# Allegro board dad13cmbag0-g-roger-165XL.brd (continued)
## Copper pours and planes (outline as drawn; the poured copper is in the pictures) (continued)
SWR_GND on IN2 (solid shape): 103.61,39.45 104.07,39.45 104.18,39.35 104.18,37.09 103.87,36.78 102.47,36.78 102.35,36.66 102.17,36.66 102.17,36.7 102.12,36.84 102.01,36.95 101.96,37.04 102.01,37.12 101.81,37.78 101.62,37.12 101.66,37.04 101.62,36.95 101.51,36.84 101.46,36.7 101.45,36.66 100.95,36.66 100.54,36.25 100.54,35.87 100.31,35.64 97.34,35.64 97.11,35.87 97.11,37.14 96.71,37.55 95.95,37.55 95.84,37.65 95.84,39.35 96.08,39.58 97.09,39.58 97.88,40.37 102.7,40.37
SWR_GND on SGND1 (solid shape): 103.54,39.52 103.62,39.47 103.72,39.45 104.07,39.45 104.18,39.35 104.18,37.09 103.87,36.78 102.58,36.78 102.48,36.76 102.4,36.71 102.34,36.66 102.17,36.66 101.81,37.01 101.46,36.66 101.05,36.66 100.95,36.64 100.87,36.58 100.62,36.33 100.56,36.25 100.54,36.15 100.54,35.87 100.31,35.64 97.35,35.64 97.11,35.87 97.11,37.04 97.1,37.14 97.04,37.22 96.79,37.47 96.7,37.53 96.61,37.55 95.95,37.55 95.84,37.65 95.84,39.35 96.08,39.58 96.99,39.58 97.08,39.6 97.17,39.65 97.88,40.36 102.7,40.36
SWR_GND on SVCC (solid shape): 103.54,39.52 103.62,39.47 103.72,39.45 104.07,39.45 104.18,39.35 104.18,37.09 103.87,36.78 102.58,36.78 102.48,36.76 102.4,36.71 102.34,36.66 102.17,36.66 101.81,37.01 101.46,36.66 101.05,36.66 100.95,36.64 100.87,36.58 100.62,36.33 100.56,36.25 100.54,36.15 100.54,35.87 100.31,35.64 97.35,35.64 97.11,35.87 97.11,37.04 97.1,37.14 97.04,37.22 96.79,37.47 96.7,37.53 96.61,37.55 95.95,37.55 95.84,37.65 95.84,39.35 96.08,39.58 96.99,39.58 97.08,39.6 97.17,39.65 97.88,40.36 102.7,40.36
SWR_GND on IN3 (solid shape): 103.41,39.65 103.41,39.22 102.9,39.22 101.6,37.93 101.17,37.93 99.53,36.28 99.53,35.69 99.48,35.64 97.34,35.64 97.11,35.87 97.11,37.14 96.71,37.55 95.95,37.55 95.84,37.65 95.84,39.35 96.07,39.58 97.09,39.58 97.88,40.37 102.7,40.37
SWR_GND on IN4 (solid shape): 103.61,39.45 104.07,39.45 104.18,39.35 104.18,37.09 103.87,36.78 102.47,36.78 102.35,36.66 102.17,36.66 102.17,36.7 102.12,36.84 102.01,36.95 101.96,37.04 102.01,37.12 101.81,37.78 101.62,37.12 101.66,37.04 101.62,36.95 101.51,36.84 101.46,36.7 101.45,36.66 100.95,36.66 100.54,36.25 100.54,35.87 100.31,35.64 97.34,35.64 97.11,35.87 97.11,37.14 96.71,37.55 95.95,37.55 95.84,37.65 95.84,39.35 96.08,39.58 97.09,39.58 97.88,40.37 102.7,40.37
SWR_GND on GND2 (solid shape): 103.61,39.45 104.07,39.45 104.18,39.35 104.18,37.09 103.87,36.78 102.47,36.78 102.34,36.66 102.24,36.66 102.19,36.7 102.19,36.72 102.13,36.86 102.03,36.97 101.99,37.05 102.03,37.13 101.81,37.78 101.6,37.13 101.64,37.05 101.6,36.97 101.49,36.86 101.44,36.72 101.43,36.7 101.38,36.66 100.95,36.66 100.54,36.25 100.54,35.87 100.31,35.64 97.35,35.64 97.11,35.87 97.11,37.14 96.71,37.55 95.95,37.55 95.84,37.65 95.84,39.35 96.08,39.58 97.09,39.58 97.88,40.37 102.7,40.37
VCHGR_BST on TOP (solid shape): 127.9,29.16 127.64,28.91 127.64,27.54 127.67,27.51 126.93,27.51 126.93,28.55 127.62,29.24 127.62,30.38 127.9,30.38
VCHGR_DH on TOP (solid shape): 128.38,29.13 128.34,29.09 128.34,28.99 128.34,28.35 128.29,28.3 127.91,28.3 127.77,28.44 127.77,28.81 128.13,29.16 128.13,30.38 128.38,30.38
VCHGR_DH on BOTTOM (solid shape): 130.46,17.15 130.46,16.31 130.26,16.11 129.22,16.11 129.09,16.24 129.09,16.69 129.6,17.2 130.41,17.2
VCHGR_DL on BOTTOM (solid shape): 126.17,20.53 126.17,19.03 126.15,19 125.36,19 125.33,19.03 125.33,20.58 125.51,20.76 125.94,20.76
VCHGR_LX on TOP (solid shape): 128.89,29.16 129.04,29.01 129.04,28.38 128.89,28.22 128.89,27.18 128.79,27.08 128.31,27.08 128.31,27.56 128.47,27.73 128.47,28.28 128.51,28.32 128.51,29.06 128.61,29.16 128.61,30.38 128.89,30.38
VCHGR_LX on BOTTOM (solid shape): 129.19,19.28 129.19,17.05 128.97,16.82 128.97,16.08 129.09,15.96 130.54,15.96 130.79,16.21 130.79,17.15 130.85,17.2 134.88,17.2 135.24,16.84 135.24,14.3 134.17,13.24 130.82,13.24 130.13,13.92 127.16,13.92 126.92,14.16 131.56,14.16 131.56,14.11 131.58,14.05 131.6,14 131.63,13.96 131.66,13.91 131.7,13.88 131.75,13.84 131.8,13.82 131.85,13.8 131.91,13.8 131.97,13.8 132.02,13.8 132.07,13.82 132.12,13.84 132.17,13.88 132.21,13.91 132.25,13.96 132.28,14 132.3,14.05 132.31,14.11 132.32,14.16 132.32,14.22 132.31,14.27 132.29,14.33 132.26,14.38 132.23,14.42 132.19,14.46 132.15,14.5 132.1,14.52 132.05,14.54 131.99,14.56 131.94,14.56 131.88,14.56 131.83,14.54 131.78,14.52 131.73,14.5 131.68,14.46 131.64,14.42 131.61,14.38 131.59,14.33 131.57,14.27 131.56,14.22 131.56,14.16 126.92,14.16 126.78,14.3 126.78,19.27 126.85,19.34 129.13,19.34
VCHGR_VCC on TOP (solid shape): 129.63,30.23 129.63,29.67 130.77,28.53 132.04,28.53 132.39,28.17 132.39,26.52 132.37,26.5 130.77,26.5 130.13,27.13 129.5,27.13 129.37,27.26 129.37,29.16 129.12,29.42 129.12,30.31 129.19,30.38 129.47,30.38
VCORE_AGND on IN2 (solid shape): outline of 1112 points within 17.68,51.07 30.31,61.37
N122118059 on TOP (solid shape): 134.71,41.48 134.71,40.21 133.92,39.43 131.62,39.43 131.62,41.19 131.68,41.25 132.06,41.25 132.06,40.37 132.37,40.37 132.37,41.25 132.72,41.25 132.72,40.37 133.03,40.37 133.03,41.25 133.49,41.25 134.05,41.81 134.38,41.81
N122232203 on TOP (solid shape): 69.63,56.37 70.57,56.37 70.7,56.24 70.7,54.89 70.52,54.72 68.95,54.72 68.74,54.92 68.74,56.39 68.79,56.44 69.56,56.44
N122232731 on TOP (solid shape): 87.46,46.54 87.46,45.75 87.39,45.67 86.57,45.67 86.45,45.8 84.67,45.8 84.54,45.93 84.54,46.46 84.64,46.56 87.44,46.56
N122232990 on IN1 (solid shape): 69.45,57.18 69.45,56.37 69.35,56.27 69.05,56.27 68.26,55.48 67.83,55.48 67.7,55.61 67.7,56.42 67.93,56.65 68.49,56.65 69.1,57.26 69.38,57.26
N122232990 on IN4 (solid shape): 69.48,57.31 69.48,56.77 69.63,56.62 69.66,56.62 69.73,56.54 69.73,56.44 69.61,56.32 69,56.32 68.64,56.67 68.64,57.26 68.82,57.43 69.35,57.43
N122416321 on TOP (solid shape): 185.68,56.16 185.68,53.73 185.63,53.67 184.35,53.67 184.31,53.71 184.31,54.41 183.63,55.1 183.63,56.01 183.8,56.19 185.66,56.19
N122446326 on BOTTOM (solid shape): 101.81,54.06 101.81,52.28 101.69,52.15 98.89,52.15 98.77,52.28 98.77,53.01 98.51,53.27 98.51,54.26 98.55,54.3 101.57,54.3
N122457781 on TOP (solid shape): 183.18,39.11 183.18,37.69 182.69,37.19 182.69,36.35 182.99,36.05 182.99,35.46 182.96,35.43 182.51,35.43 182.46,35.48 182.46,35.67 182.2,35.92 182.2,38.38 182.22,38.4 182.22,39.13 182.48,39.4 182.89,39.4
N122457865 on TOP (solid shape): 183.75,32.65 183.75,32.06 183.57,31.88 183.32,31.88 182.89,31.45 182.89,31.02 183.5,30.41 183.5,29.86 183.47,29.83 182.97,29.83 182.92,29.89 182.92,30.18 182.25,30.84 182.25,31.73 182.71,32.19 182.71,32.62 182.94,32.85 183.55,32.85
N122829159 on TOP (solid shape): 141.74,41.68 141.74,41.08 142.1,40.73 143.06,40.73 143.21,40.58 143.21,39.33 143.15,39.28 140.67,39.28 140.15,39.28 140.06,39.36 140.06,40.86 141.06,41.85 141.58,41.85
N122829607 on TOP (solid shape): 157.92,39.81 157.92,39.48 157.01,38.56 157.01,38.05 156.98,38.03 156.22,38.03 156.19,38.05 156.19,40.01 156.25,40.06 157.67,40.06
N122832375 on TOP (solid shape): 125.18,37.39 125.18,35.97 124.67,35.46 123.45,35.46 123.45,35.72 122.49,35.72 122.49,35.34 121.98,34.83 120.2,34.83 120.15,34.88 120.15,35.62 120.46,35.92 121.6,35.92 121.7,36.02 121.7,36.73 121.83,36.86 124.01,36.86 124.7,37.55 125.03,37.55
N122832615 on TOP (solid shape): 119.82,32.16 119.82,31.42 119.75,31.35 117.76,31.35 117.71,31.4 117.71,32.19 117.82,32.29 119.69,32.29
N122833803 on TOP (solid shape): 102.47,66.22 102.47,65.84 102.37,65.74 102.07,65.74 101.18,64.85 100.31,64.85 100.26,64.9 100.26,66.27 100.34,66.35 102.35,66.35
N122833805 on BOTTOM (solid shape): 102.94,64.86 103.51,64.86 104.17,64.21 104.17,63.99 103.17,63.99 103.17,63.78 104.17,63.78 104.17,63.59 103.17,63.59 103.17,63.39 104.17,63.39 104.17,63.19 103.17,63.19 103.17,62.99 104.17,62.99 104.17,62.81 104.15,62.8 102.83,62.8 102.83,62.79 102.42,62.79 102.14,62.51 102.14,61.6 101.66,61.12 101.66,60.71 100.82,59.87 100.82,58.73 100.75,58.65 99.4,58.65 98.13,59.92 98.13,65.03 98.18,65.08 102.73,65.08
N122833835 on BOTTOM (solid shape): 103.15,62.59 104.15,62.59 104.17,62.58 104.17,62.41 104.15,62.39 103.12,62.39 103.12,62.39 102.98,62.39 102.93,62.34 102.93,61.45 102.63,61.14 102.63,58.81 102.5,58.68 101.36,58.68 101.25,58.78 101.25,60.05 101.81,60.61 101.81,61.07 102.3,61.55 102.3,62.41 102.5,62.62 103.12,62.62
N122833837 on BOTTOM (solid shape): 102.04,57.23 99.27,57.23 99.1,57.41 99.1,57.81 99.32,58.04 102.04,58.04
N122834634 on BOTTOM (solid shape): 181.43,10.47 182.68,10.47 182.69,10.46 182.69,10.17 181.71,10.17 181.71,9.97 182.69,9.97 182.69,9.67 181.71,9.67 181.71,9.47 182.69,9.47 182.69,9.2 182.67,9.18 181.37,9.18 181.18,8.99 181.18,8.19 181.17,8.19 179.2,8.19 179.16,8.23 179.16,10.66 179.18,10.68 181.22,10.68
N122836623 on BOTTOM (solid shape): 16.62,58.91 17.23,58.91 17.31,58.83 17.31,58.37 17.21,58.27 16.57,58.27 16.47,58.17 15.48,58.17 15.45,58.2 15.45,59.01 15.53,59.08 16.44,59.08
N122836643 on BOTTOM (solid shape): 17.26,57.94 17.26,57.18 17.24,57.17 17.24,56.74 17.02,56.51 16.7,56.51 15.99,55.8 15.99,55.16 15.96,55.14 15.83,55.14 15.8,55.17 15.8,56.02 16.65,56.88 16.65,57.99 16.67,58.02 17.18,58.02
N122836645 on BOTTOM (solid shape): 16.24,57.56 16.24,56.8 15.58,56.14 15.58,55.15 15.53,55.1 15.45,55.1 15.4,55.15 15.4,56.17 15.38,56.19 15.38,57.51 15.48,57.61 16.19,57.61
N122836651 on BOTTOM (solid shape): 22.13,61.12 22.13,58.98 22.59,58.53 22.59,58.32 22.57,58.3 21.83,58.3 21.68,58.45 21.68,59.44 21.35,59.77 21.35,61.17 21.47,61.29 21.96,61.29
N122837549 on BOTTOM (solid shape): 10.53,46.13 10.53,45.42 10.55,45.39 11.44,45.39 11.47,45.37 11.47,44.89 11.41,44.84 9.31,44.84 9.28,44.86 9.28,46.18 10.47,46.18
N122837792 on BOTTOM (solid shape): 15.17,52.4 15.17,47.75 15.16,47.73 13.32,47.73 13.28,47.7 13.28,47.19 13.3,47.17 15.16,47.17 15.17,47.16 15.17,45.62 15.1,45.55 11.06,45.55 10.96,45.65 10.96,46.18 11.14,46.36 11.77,46.36 11.9,46.49 11.9,49.01 12.32,49.43 12.32,49.44 12.99,50.11 12.99,52.51 15.07,52.51
N123081950 on TOP (solid shape): 193.99,38.76 193.99,37.34 194.47,36.86 194.47,36.12 192.92,36.12 192.77,36.28 192.77,37.04 192.44,37.37 191.96,37.37 191.83,37.49 191.83,38.03 192.01,38.21 192.39,38.21 193.2,39.02 193.74,39.02
N123329056 on TOP (solid shape): 159.92,45.82 159.92,45.54 159.4,45.54 159.35,45.49 159.35,45.37 159.41,45.32 159.92,45.32 159.92,44.01 159.67,43.77 158.18,43.77 157.9,44.05 157.9,45.04 157.82,45.11 157.82,45.67 157.96,45.81 158.8,45.81 158.81,45.82 159.92,45.82
N123838543 on TOP (solid shape): 131.29,40.83 131.29,37.8 131.23,37.75 130.26,37.75 130.21,37.8 130.21,38.27 130.3,38.36 130.3,38.72 130.23,38.79 130.23,39.26 130.34,39.37 130.34,40.88 130.49,41.03 131.09,41.03
N124553844 on TOP (solid shape): 27.8,45.98 27.8,44.94 26.93,44.94 26.35,45.52 25.21,45.52 25,45.72 25,46.33 24.65,46.69 24.65,47.55 24.75,47.65 26.12,47.65
N124557432 on TOP (solid shape): 116.37,18.8 116.37,17.61 116.16,17.4 116.16,16.54 116.09,16.46 114.26,16.46 113.29,17.43 113.29,18.78 113.4,18.88 116.29,18.88
N124557495 on TOP (solid shape): 118.02,22.23 118.02,20.1 117.56,19.64 116.24,19.64 116.19,19.69 116.19,20.78 116.62,21.21 116.62,22.25 116.77,22.41 117.84,22.41
N126069331 on TOP (solid shape): 94.8,27.03 95.66,27.03 95.7,26.98 95.7,26.9 95.64,26.84 94.97,26.84 94.96,26.83 94.96,26.65 94.97,26.64 95.7,26.64 95.72,26.62 95.72,26.12 95.59,25.99 95.39,25.99 95.26,25.86 95.26,25.33 95.16,25.23 94.04,25.23 93.3,25.96 93.3,27.79 94.04,27.79
N126069345 on TOP (solid shape): 94.66,31.16 96.13,31.16 96.2,31.09 96.2,29.65 95.71,29.16 95.71,28.93 95.63,28.85 94.96,28.85 94.96,28.64 95.66,28.64 95.71,28.58 95.71,28.5 95.67,28.45 94.97,28.45 94.96,28.46 94.59,28.46 94.37,28.68 94.37,29.05 94.21,29.21 94.21,29.81 93.41,30.61 93.41,31.04 93.53,31.17 94.66,31.17
N127565521 on TOP (solid shape): 137.8,38.74 137.8,38.38 136.76,37.34 136.31,37.34 135.87,37.77 134.76,37.77 134.72,37.81 134.72,38.21 134.73,38.22 135.51,38.22 135.53,38.24 135.53,38.39 135.51,38.41 134.74,38.41 134.72,38.43 134.72,38.71 134.74,38.72 135.51,38.72 135.53,38.74 136.05,38.74 136.13,38.82 137.73,38.82
N127566567 on TOP (solid shape): 143.88,49.24 143.88,47.05 142.48,45.65 141.64,45.65 141.56,45.72 141.56,47.53 141.61,47.58 142.12,47.58 142.3,47.76 142.3,49.25 142.48,49.42 143.7,49.42
N127566661 on BOTTOM (solid shape): 122.97,24.24 122.97,23.58 122.98,23.58 122.98,23.46 122.98,23.46 122.98,23.12 122.97,23.12 121.98,23.12 121.78,23.32 121.78,24.26 121.88,24.36 122.84,24.36
N127566722 on BOTTOM (solid shape): 119.34,16.57 119.34,14.56 119.26,14.48 118.63,14.48 118.55,14.56 118.55,15.09 118.73,15.27 118.73,16.41 118.91,16.59 119.31,16.59
N127566838 on TOP (solid shape): 128.84,26.75 128.84,23.3 128.53,22.99 127.21,22.99 126.93,23.27 126.93,26.88 128.71,26.88
N127566860 on BOTTOM (solid shape): 123.2,16.82 123.2,16.72 124.19,15.73 124.19,14.49 124.16,14.46 123.28,14.46 123.24,14.5 123.24,15.14 123.23,15.14 122.02,15.14 122.02,15.14 121.89,15.14 121.87,15.12 121.87,14.5 121.83,14.46 120.7,14.46 120.6,14.55 120.6,14.84 120.46,14.99 119.69,14.99 119.64,15.04 119.64,16.57 119.67,16.59 119.98,16.59 119.98,15.79 120.32,15.79 120.32,16.59 120.64,16.59 120.64,15.78 120.97,15.78 120.97,16.59 121.7,16.59 122.13,17.02 123,17.02
N127567004 on BOTTOM (solid shape): 127.37,24.44 127.37,22.84 127.34,22.81 126.69,22.81 126.68,22.81 126.68,21.47 126.7,21.45 127.36,21.45 127.37,21.44 127.37,20.54 127.36,20.53 126.43,20.53 126.04,20.91 125.13,20.91 124.85,20.63 124.85,19.38 124.77,19.31 123.73,19.31 123.66,19.38 123.66,20.98 123.5,21.14 123.5,23.55 124.72,24.77 127.04,24.77
N127567165 on TOP (solid shape): 133.25,25.71 133.43,25.67 133.61,25.71 134.07,25.71 134.1,25.68 134.1,24.59 134.04,24.53 134.01,24.54 133.81,24.56 133.62,24.49 132.75,24.49 132.45,24.19 132.45,23.07 132.37,22.99 129.68,22.99 129.35,23.32 129.35,24.97 130.08,25.71

Small or netless copper shapes (teardrops, artwork), in the pictures only: 45 on TOP, 66 on BOTTOM, 49 on IN1, 16 on IN2, 56 on IN3, 55 on IN4

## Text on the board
Ref Des/Silkscreen Bottom: D | A | B | E | C | F | MODEL:D13C | REV:G | RGF2V | DAD13CMBAG0
User.Comments: 79.0x87.0 | PARTITION_2
Ref Des/Silkscreen Top: A | C | B | D | E | DAD13CMBAG0 | RGF2V | REV:G | MODEL:D13C
GND: GND | 2
GND2: GND2 | 9
User.13: +SMDDR_VREF_CA | +1.05V_RUN | +V1.05DX_MODPHY | +1.05V_SUS | SWR_GND | +LED_BL | +VCCIN | GND | +5V_ALW | +PWR_SRC | +3.3V_RUN | +3.3V_ALW
User.29: SWR_GND | GND
User.45: FIGURE | TYPE | Oblong | SIZE | 71.0x28.0 | 75.0x24.0 | 77.0x22.0 | 79.0x28.0 | DRILL CHART: TOP to BOTTOM | ALL UNITS ARE IN MILS | PLATED | NON-PLATED | ROTATION | 0.000 | 90.000 | QTY | 2 | 4 | 1 | 11 | Circle | 4.0 | DRILL CHART: TOP to GND | DRILL CHART: GND to IN1 | - | 1619 | 859 | 10.0 | 12.0 | 14.0 | 20.0 | 30.0 | 31.0 | 91.0 | 102.0 | 142.0 | 26.0 | 28.0 | 32.0 | 37.0 | 43.0 | 63.0 | 79.0 | 8.0 | DRILL CHART: IN1 to IN4 | DRILL CHART: GND2 to BOTTOM | DRILL CHART: IN3 to IN4 | DRILL CHART: IN1 to IN2 | DRILL CHART: IN4 to GND2 | 69 | 961 | 13 | 379 | 10 | 9 | 6 | 3 | 1466 | 690 | 2268 | 455 | 345 | 1394 | TOTAL HOLES:
